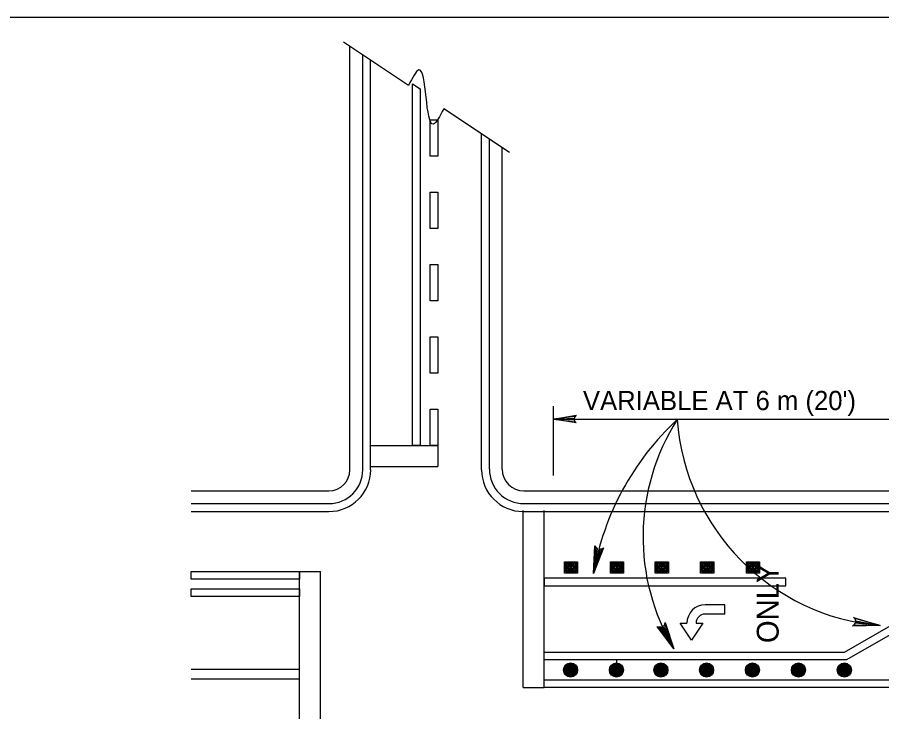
# Model space of a CAD drawing. Extents: x 639362 to 641108, y 298458 to 299646.
# Drawn here: x 639788.7 to 639923.9, y 298928.7 to 299037.2 of the extents above; entities that cross this region are included whole.
import ezdxf

# ---------------------------------------------------------------- set-up
doc = ezdxf.new("R2010")
doc.units = 0
for name, color, linetype in [('1', 7, 'Continuous'), ('2', 7, 'Continuous'), ('3', 7, 'Continuous')]:
    doc.layers.add(name, color=color, linetype=linetype)

# ---------------------------------------------------------------- blocks, each defined once
blk = doc.blocks.new('RARROW')
at = {"layer": '3'}
blk.add_lwpolyline([(-2.2695, 0.285), (-2.184875, 0.12075), (0, 0), (-2.2695, 0.285), (-2.38575, 0.384625), (0, 0), (-2.183125, -0.108), (-2.262875, -0.2705), (0, 0), (-2.38575, -0.379125), (-2.262875, -0.2705)], dxfattribs=at)

msp = doc.modelspace()

# ---------------------------------------------------------------- linework, layer by layer
at = {"layer": '1'}
msp.add_line((639403.27, 299037.19), (640189.27, 299037.19), dxfattribs=at)
at = {"layer": '2'}
for p, q in [((639849.91, 299026.56), (639839.75, 299033.33)), ((639840.75, 298966.48), (639840.75, 299032.67)), ((639842.75, 298966.48), (639842.75, 299031.33)), ((639843.98, 298966.48), (639843.98, 299030.51)), ((639850.53, 298970.29), (639850.53, 299026.79)), ((639850.53, 299026.79), (639851.73, 299025.99)), ((639851.73, 299025.99), (639851.73, 298970.29)), ((639865.68, 299016.04), (639855.4, 299022.9)), ((639861.32, 298966.48), (639861.32, 299018.96)), ((639862.55, 298966.6), (639862.55, 299018.13)), ((639864.55, 298966.6), (639864.55, 299016.8)), ((639872.53, 298976.4), (639872.53, 298965.6)), ((639872.53, 298974.4), (639941.89, 298974.4)), ((639843.98, 298970.29), (639854.47, 298970.29)), ((639851.73, 298970.29), (639850.53, 298970.29)), ((639854.47, 298970.29), (639854.47, 298966.99)), ((639843.97, 298966.99), (639854.47, 298966.99)), ((639815.93, 298963.2), (639837.47, 298963.2)), ((639867.95, 298963.2), (639989.83, 298963.2)), ((639815.93, 298961.2), (639837.47, 298961.2)), ((639867.95, 298961.2), (639989.83, 298961.2)), ((639815.93, 298959.96), (639837.47, 298959.96)), ((639867.83, 298932.45), (639867.83, 298960.1)), ((639867.83, 298959.96), (639989.83, 298959.96)), ((639871.13, 298932.45), (639871.13, 298960.1)), ((639874.29, 298950.34), (639874.29, 298952.12)), ((639874.29, 298952.12), (639876.33, 298952.12)), ((639874.47, 298950.52), (639874.47, 298951.94)), ((639874.47, 298951.94), (639876.16, 298951.94)), ((639874.65, 298950.7), (639874.65, 298951.76)), ((639874.65, 298951.76), (639875.98, 298951.76)), ((639875.98, 298951.76), (639875.98, 298950.7)), ((639876.16, 298951.94), (639876.16, 298950.52)), ((639876.33, 298952.12), (639876.33, 298950.34)), ((639881.47, 298950.34), (639881.47, 298952.12)), ((639881.47, 298952.12), (639883.51, 298952.12)), ((639881.65, 298950.52), (639881.65, 298951.94)), ((639881.65, 298951.94), (639883.34, 298951.94)), ((639881.83, 298950.7), (639881.83, 298951.76)), ((639881.83, 298951.76), (639883.16, 298951.76)), ((639883.16, 298951.76), (639883.16, 298950.7)), ((639883.34, 298951.94), (639883.34, 298950.52)), ((639883.51, 298952.12), (639883.51, 298950.34)), ((639888.48, 298950.34), (639888.48, 298952.12)), ((639888.48, 298952.12), (639890.52, 298952.12)), ((639888.66, 298950.52), (639888.66, 298951.94)), ((639888.66, 298951.94), (639890.34, 298951.94)), ((639888.83, 298950.7), (639888.83, 298951.76)), ((639888.83, 298951.76), (639890.16, 298951.76)), ((639890.16, 298951.76), (639890.16, 298950.7)), ((639890.34, 298951.94), (639890.34, 298950.52)), ((639890.52, 298952.12), (639890.52, 298950.34)), ((639895.57, 298950.34), (639895.57, 298952.12)), ((639895.57, 298952.12), (639897.61, 298952.12)), ((639895.75, 298950.52), (639895.75, 298951.94)), ((639895.75, 298951.94), (639897.43, 298951.94)), ((639895.93, 298950.7), (639895.93, 298951.76)), ((639895.93, 298951.76), (639897.26, 298951.76)), ((639897.26, 298951.76), (639897.26, 298950.7)), ((639897.43, 298951.94), (639897.43, 298950.52)), ((639897.61, 298952.12), (639897.61, 298950.34)), ((639902.75, 298950.34), (639902.75, 298952.12)), ((639902.75, 298952.12), (639904.79, 298952.12)), ((639902.93, 298950.52), (639902.93, 298951.94)), ((639902.93, 298951.94), (639904.61, 298951.94)), ((639903.11, 298950.7), (639903.11, 298951.76)), ((639903.11, 298951.76), (639904.43, 298951.76)), ((639904.43, 298951.76), (639904.43, 298950.7)), ((639904.61, 298951.94), (639904.61, 298950.52)), ((639904.79, 298952.12), (639904.79, 298950.34)), ((639918.03, 298937.96), (639941.89, 298951.73)), ((639815.93, 298949.39), (639815.93, 298950.59)), ((639815.93, 298950.59), (639832.85, 298950.59)), ((639832.85, 298922.95), (639832.85, 298950.59)), ((639832.85, 298950.59), (639836.15, 298950.59)), ((639832.85, 298950.59), (639832.85, 298949.39)), ((639836.15, 298922.95), (639836.15, 298950.59)), ((639876.16, 298950.52), (639874.47, 298950.52)), ((639875.98, 298950.7), (639874.65, 298950.7)), ((639874.83, 298951.58), (639875.8, 298951.58)), ((639874.83, 298950.88), (639874.83, 298951.58)), ((639875.8, 298950.88), (639874.83, 298950.88)), ((639875, 298951.05), (639875, 298951.41)), ((639875, 298951.41), (639875.62, 298951.41)), ((639875.62, 298951.05), (639875, 298951.05)), ((639875.18, 298951.23), (639875.45, 298951.23)), ((639875.62, 298951.41), (639875.62, 298951.05)), ((639875.8, 298951.58), (639875.8, 298950.88)), ((639883.34, 298950.52), (639881.65, 298950.52)), ((639883.16, 298950.7), (639881.83, 298950.7)), ((639882.01, 298951.58), (639882.98, 298951.58)), ((639882.01, 298950.88), (639882.01, 298951.58)), ((639882.98, 298950.88), (639882.01, 298950.88)), ((639882.18, 298951.05), (639882.18, 298951.41)), ((639882.18, 298951.41), (639882.8, 298951.41)), ((639882.8, 298951.05), (639882.18, 298951.05)), ((639882.36, 298951.23), (639882.63, 298951.23)), ((639882.8, 298951.41), (639882.8, 298951.05)), ((639882.98, 298951.58), (639882.98, 298950.88)), ((639890.34, 298950.52), (639888.66, 298950.52)), ((639890.16, 298950.7), (639888.83, 298950.7)), ((639889.01, 298951.58), (639889.99, 298951.58)), ((639889.01, 298950.88), (639889.01, 298951.58)), ((639889.99, 298950.88), (639889.01, 298950.88)), ((639889.19, 298951.05), (639889.19, 298951.41)), ((639889.19, 298951.41), (639889.81, 298951.41)), ((639889.81, 298951.05), (639889.19, 298951.05)), ((639889.36, 298951.23), (639889.63, 298951.23)), ((639889.81, 298951.41), (639889.81, 298951.05)), ((639889.99, 298951.58), (639889.99, 298950.88)), ((639897.43, 298950.52), (639895.75, 298950.52)), ((639897.26, 298950.7), (639895.93, 298950.7)), ((639896.1, 298951.58), (639897.08, 298951.58)), ((639896.1, 298950.88), (639896.1, 298951.58)), ((639897.08, 298950.88), (639896.1, 298950.88)), ((639896.28, 298951.05), (639896.28, 298951.41)), ((639896.28, 298951.41), (639896.9, 298951.41)), ((639896.9, 298951.05), (639896.28, 298951.05)), ((639896.46, 298951.23), (639896.72, 298951.23)), ((639896.9, 298951.41), (639896.9, 298951.05)), ((639897.08, 298951.58), (639897.08, 298950.88)), ((639904.61, 298950.52), (639902.93, 298950.52)), ((639904.43, 298950.7), (639903.11, 298950.7)), ((639903.28, 298951.58), (639904.26, 298951.58)), ((639903.28, 298950.88), (639903.28, 298951.58)), ((639904.26, 298950.88), (639903.28, 298950.88)), ((639903.46, 298951.05), (639903.46, 298951.41)), ((639903.46, 298951.41), (639904.08, 298951.41)), ((639904.08, 298951.05), (639903.46, 298951.05)), ((639903.64, 298951.23), (639903.9, 298951.23)), ((639904.08, 298951.41), (639904.08, 298951.05)), ((639904.26, 298951.58), (639904.26, 298950.88)), ((639942.21, 298950.53), (639918.36, 298936.76)), ((639832.85, 298949.39), (639815.93, 298949.39)), ((639908.88, 298949.57), (639871.13, 298949.57)), ((639871.13, 298949.57), (639871.13, 298948.35)), ((639876.33, 298950.34), (639874.29, 298950.34)), ((639883.51, 298950.34), (639881.47, 298950.34)), ((639890.52, 298950.34), (639888.48, 298950.34)), ((639897.61, 298950.34), (639895.57, 298950.34)), ((639904.79, 298950.34), (639902.75, 298950.34)), ((639908.88, 298948.35), (639908.88, 298949.57)), ((639815.93, 298946.66), (639815.93, 298947.86)), ((639815.93, 298947.86), (639832.85, 298947.86)), ((639832.85, 298947.86), (639832.85, 298946.66)), ((639871.13, 298948.35), (639908.88, 298948.35)), ((639832.85, 298946.66), (639815.93, 298946.66)), ((639899.35, 298945.37), (639896.27, 298945.37)), ((639899.35, 298943.94), (639899.35, 298945.37)), ((639899.35, 298943.94), (639896.27, 298943.94)), ((639894.14, 298939.85), (639892.36, 298942.52)), ((639892.36, 298942.52), (639893.42, 298942.52)), ((639895.91, 298942.52), (639894.14, 298939.85)), ((639894.85, 298942.52), (639895.91, 298942.52)), ((639871.13, 298936.76), (639871.13, 298937.96)), ((639871.13, 298937.96), (639918.03, 298937.96)), ((639918.36, 298936.76), (639871.13, 298936.76)), ((639882.4, 298936.76), (639882.4, 298935.19)), ((639815.93, 298935.33), (639832.85, 298935.33)), ((639815.93, 298933.83), (639832.85, 298933.83)), ((639871.13, 298932.45), (639871.13, 298933.65)), ((639871.13, 298933.65), (639989.73, 298933.65)), ((639867.83, 298932.45), (639871.13, 298932.45)), ((639989.83, 298932.45), (639871.13, 298932.45))]:
    msp.add_line(p, q, dxfattribs=at)
for points in [[(639853.27, 299021.16), (639854.47, 299021.16), (639854.47, 299015.51), (639853.27, 299015.51)], [(639853.27, 299009.86), (639854.47, 299009.86), (639854.47, 299004.2), (639853.27, 299004.2)], [(639853.27, 298998.55), (639854.47, 298998.55), (639854.47, 298992.9), (639853.27, 298992.9)], [(639853.27, 298987.25), (639854.47, 298987.25), (639854.47, 298981.59), (639853.27, 298981.59)], [(639853.27, 298975.94), (639854.47, 298975.94), (639854.47, 298970.29), (639853.27, 298970.29)]]:
    msp.add_lwpolyline(points, close=True, dxfattribs=at)
for points in [[(639880.16, 298954.15), (639879.84, 298954.06), (639878.81, 298950.25), (639880.16, 298954.15), (639880.38, 298954.31), (639878.81, 298950.25), (639879.44, 298954.14), (639879.18, 298954.34), (639878.81, 298950.25), (639879.04, 298954.6), (639879.18, 298954.34)], [(639889.95, 298942.34), (639889.75, 298942.07), (639891.39, 298938.49), (639889.95, 298942.34), (639890.01, 298942.61), (639891.39, 298938.49), (639889.39, 298941.88), (639889.06, 298941.87), (639891.39, 298938.49), (639888.79, 298941.97), (639889.06, 298941.87)], [(639919.66, 298943.22), (639919.77, 298942.9), (639923.63, 298942.14), (639919.66, 298943.22), (639919.48, 298943.42), (639923.63, 298942.14), (639919.71, 298942.49), (639919.53, 298942.23), (639923.63, 298942.14), (639919.28, 298942.06), (639919.53, 298942.23)]]:
    msp.add_lwpolyline(points, dxfattribs=at)
for centre, radius in [((639875.24, 298935.2), 1.1), ((639875.24, 298935.2), 1.02), ((639875.24, 298935.2), 0.946), ((639875.24, 298935.2), 0.868), ((639875.24, 298935.2), 0.789), ((639875.24, 298935.2), 0.711), ((639875.24, 298935.2), 0.633), ((639875.24, 298935.2), 0.554), ((639875.24, 298935.2), 0.476), ((639875.24, 298935.2), 0.398), ((639875.24, 298935.2), 0.32), ((639882.4, 298935.19), 1.1), ((639882.4, 298935.19), 1.02), ((639882.4, 298935.19), 0.946), ((639882.4, 298935.19), 0.868), ((639882.4, 298935.19), 0.789), ((639882.4, 298935.19), 0.711), ((639882.4, 298935.19), 0.633), ((639882.4, 298935.19), 0.554), ((639882.4, 298935.19), 0.476), ((639882.4, 298935.19), 0.398), ((639882.4, 298935.19), 0.32), ((639889.36, 298935.19), 1.1), ((639889.36, 298935.19), 1.02), ((639889.36, 298935.19), 0.946), ((639889.36, 298935.19), 0.868), ((639889.36, 298935.19), 0.789), ((639889.36, 298935.19), 0.711), ((639889.36, 298935.19), 0.633), ((639889.36, 298935.19), 0.554), ((639889.36, 298935.19), 0.476), ((639889.36, 298935.19), 0.398), ((639889.36, 298935.19), 0.32), ((639896.5, 298935.19), 1.1), ((639896.5, 298935.19), 1.02), ((639896.5, 298935.19), 0.946), ((639896.5, 298935.19), 0.868), ((639896.5, 298935.19), 0.789), ((639896.5, 298935.19), 0.711), ((639896.5, 298935.19), 0.633), ((639896.5, 298935.19), 0.554), ((639896.5, 298935.19), 0.476), ((639896.5, 298935.19), 0.398), ((639896.5, 298935.19), 0.32), ((639903.67, 298935.19), 1.1), ((639903.67, 298935.19), 1.02), ((639903.67, 298935.19), 0.946), ((639903.67, 298935.19), 0.868), ((639903.67, 298935.19), 0.789), ((639903.67, 298935.19), 0.711), ((639903.67, 298935.19), 0.633), ((639903.67, 298935.19), 0.554), ((639903.67, 298935.19), 0.476), ((639903.67, 298935.19), 0.398), ((639903.67, 298935.19), 0.32), ((639910.85, 298935.19), 1.1), ((639910.85, 298935.19), 1.02), ((639910.85, 298935.19), 0.946), ((639910.85, 298935.19), 0.868), ((639910.85, 298935.19), 0.789), ((639910.85, 298935.19), 0.711), ((639910.85, 298935.19), 0.633), ((639910.85, 298935.19), 0.554), ((639910.85, 298935.19), 0.476), ((639910.85, 298935.19), 0.398), ((639910.85, 298935.19), 0.32), ((639918.03, 298935.19), 1.1), ((639918.03, 298935.19), 1.02), ((639918.03, 298935.19), 0.946), ((639918.03, 298935.19), 0.868), ((639918.03, 298935.19), 0.789), ((639918.03, 298935.19), 0.711), ((639918.03, 298935.19), 0.633), ((639918.03, 298935.19), 0.554), ((639918.03, 298935.19), 0.476), ((639918.03, 298935.19), 0.398), ((639918.03, 298935.19), 0.32), ((639875.24, 298935.2), 0.241), ((639875.24, 298935.2), 0.163), ((639875.24, 298935.2), 0.0846), ((639882.4, 298935.19), 0.241), ((639882.4, 298935.19), 0.163), ((639882.4, 298935.19), 0.0846), ((639889.36, 298935.19), 0.241), ((639889.36, 298935.19), 0.163), ((639889.36, 298935.19), 0.0846), ((639896.5, 298935.19), 0.241), ((639896.5, 298935.19), 0.163), ((639896.5, 298935.19), 0.0846), ((639903.67, 298935.19), 0.241), ((639903.67, 298935.19), 0.163), ((639903.67, 298935.19), 0.0846), ((639910.85, 298935.19), 0.241), ((639910.85, 298935.19), 0.163), ((639910.85, 298935.19), 0.0846), ((639918.03, 298935.19), 0.241), ((639918.03, 298935.19), 0.163), ((639918.03, 298935.19), 0.0846)]:
    msp.add_circle(centre, radius, dxfattribs=at)
for centre, radius, start, end in [((639920.86, 298942.97), 42.67, 132.7254, 170.1774), ((639920.64, 298955.99), 34.08, 147.4602, 210.8991), ((639926.61, 298976.8), 34.79, 184.0856, 265.0963), ((639867.95, 298966.6), 5.4, 180, 270), ((639867.95, 298966.6), 3.4, 180, 270), ((639837.47, 298966.48), 5.28, 270, 0), ((639837.47, 298966.48), 6.52, 270, 0), ((639837.47, 298966.48), 3.28, 270, 0), ((639867.83, 298966.48), 6.52, 180, 270), ((639896.27, 298942.52), 2.85, 90, 180), ((639896.27, 298942.52), 1.42, 90, 180)]:
    msp.add_arc(centre, radius, start, end, dxfattribs=at)
msp.add_spline([(639855.4, 299022.9), (639853.79, 299020.49), (639851.51, 299028.97), (639849.91, 299026.56)], degree=3, dxfattribs=at)

# ---------------------------------------------------------------- block references
at = {"layer": '2', "xscale": 1.5089217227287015, "yscale": 1.5711553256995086, "rotation": 180}
msp.add_blockref('RARROW', (639872.53, 298974.4), dxfattribs=at)

# ---------------------------------------------------------------- texts
at = {"layer": '2'}
msp.add_text("VARIABLE AT 6 m (20')", height=3, dxfattribs=at).set_placement((639877.17, 298975.81))
msp.add_text('ONLY', height=3.414, rotation=90, dxfattribs=at).set_placement((639907.76, 298939.4))

doc.saveas('drawing.dxf')
